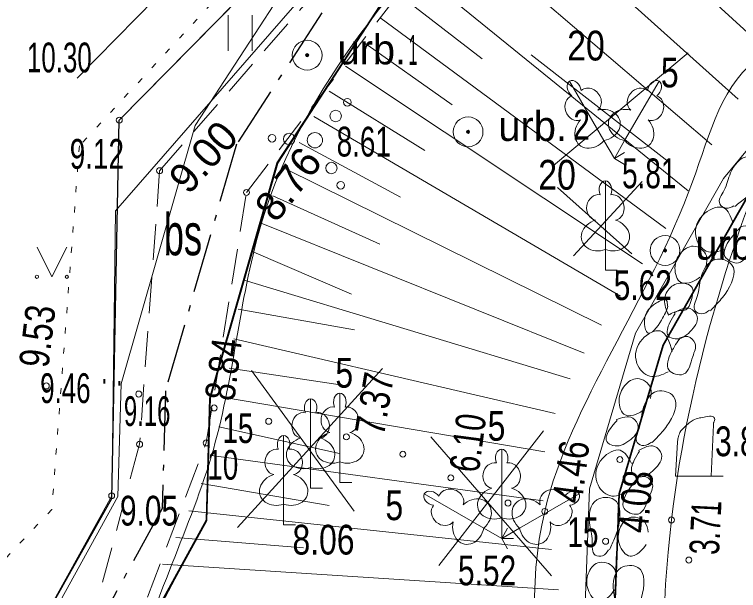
# Model space of a CAD drawing. Extents: x 514052 to 514314, y 297701 to 297876.
# Drawn here: x 514231.91 to 514244.06, y 297772.58 to 297782.26 of the extents above; entities that cross this region are included whole.
import ezdxf
from ezdxf.enums import TextEntityAlignment as Align

# ---------------------------------------------------------------- set-up
doc = ezdxf.new("R2010")
doc.units = 0
doc.header["$LTSCALE"] = 0.2
for name, pattern in [('DOT_DASHED', [7.7, 5, -1.2, 0.3, -1.2]), ('DOTTED', [1.5, 0.3, -1.2]), ('MEDIUM_DASHED', [4.5, 3, -1.5])]:
    doc.linetypes.add(name, pattern=pattern)
for name, color, linetype, lineweight in [('1', 7, 'Continuous', 13), ('11', 7, 'Continuous', 35), ('19', 7, 'Continuous', 25), ('35', 7, 'Continuous', 25), ('5', 7, 'Continuous', 13), ('55', 7, 'Continuous', 13), ('57', 7, 'DOTTED', 13), ('6', 7, 'Continuous', 13), ('61', 7, 'Continuous', 13), ('62', 7, 'Continuous', 13), ('63', 7, 'Continuous', 13)]:
    doc.layers.add(name, color=color, linetype=linetype, lineweight=lineweight)
for name, color, linetype in [('10', 7, 'Continuous'), ('12', 7, 'Continuous'), ('8', 7, 'Continuous')]:
    doc.layers.add(name, color=color, linetype=linetype)

msp = doc.modelspace()

# ---------------------------------------------------------------- hatches: boundary and pattern name
at = {"layer": '6'}
for points in [[(514236.8473, 297781.5754, 1), (514236.7942, 297781.5754, 1)], [(514239.5483, 297780.2884, 1), (514239.4952, 297780.2884, 1)], [(514242.854, 297778.2947, 1), (514242.801, 297778.2947, 1)]]:
    msp.add_hatch(color=256, dxfattribs=at).paths.add_polyline_path(points)

# ---------------------------------------------------------------- linework, layer by layer
at = {"layer": '1'}
for p, q in [((514240.629, 297785.257), (514244.562, 297781.634)), ((514239.956, 297784.518), (514244.054, 297780.838)), ((514239.295, 297783.768), (514243.612, 297780.068)), ((514238.654, 297783), (514243.216, 297779.299)), ((514238.343, 297782.608), (514239.757, 297781.513)), ((514238.041, 297782.21), (514242.841, 297778.665)), ((514237.747, 297781.805), (514239.252, 297780.744)), ((514237.464, 297781.393), (514242.451, 297778.071)), ((514237.192, 297780.973), (514238.797, 297779.976)), ((514236.933, 297780.546), (514242.082, 297777.527)), ((514236.688, 297780.11), (514238.39, 297779.192)), ((514236.458, 297779.666), (514241.759, 297777.039)), ((514236.244, 297779.214), (514238.041, 297778.403)), ((514236.047, 297778.755), (514241.471, 297776.57)), ((514235.885, 297778.282), (514237.565, 297777.563)), ((514235.762, 297777.798), (514241.238, 297776.14)), ((514235.665, 297777.307), (514237.618, 297776.964)), ((514235.587, 297776.813), (514240.986, 297775.559)), ((514235.513, 297776.319), (514237.484, 297776.024)), ((514235.435, 297775.825), (514240.811, 297774.914)), ((514235.339, 297775.334), (514237.363, 297774.888)), ((514235.215, 297774.85), (514240.784, 297774.089)), ((514235.044, 297774.38), (514237.188, 297774.014)), ((514234.837, 297773.925), (514240.922, 297773.271)), ((514234.615, 297773.477), (514236.758, 297773.298)), ((514234.394, 297773.029), (514241.041, 297772.596))]:
    msp.add_line(p, q, dxfattribs=at)
msp.add_spline([(514260.862, 297805.466), (514258.749, 297804.839), (514257.459, 297803.011), (514254.953, 297800.933), (514250.105, 297795.245), (514240.136, 297784.718), (514236.07, 297778.812), (514235.246, 297774.955), (514233.92, 297771.109), (514234.456, 297764.804)], degree=3, dxfattribs=at)
at = {"layer": '11'}
msp.add_lwpolyline([(514232.958, 297781.189), (514235.602, 297783.886), (514241.55, 297789.883)], dxfattribs=at)
at = {"layer": '19', "lineweight": 13}
msp.add_spline([(514243.205, 297765.058), (514242.936, 297773.769), (514245.025, 297781.038), (514246.54, 297783.925), (514249.054, 297787.013), (514257.225, 297795.21), (514260.154, 297798.886), (514267.863, 297801.516), (514273.305, 297805.826), (514276.583, 297807.615)], degree=3, dxfattribs=at)
at = {"layer": '35'}
msp.add_lwpolyline([(514231.97, 297771.331), (514233.541, 297774.128), (514233.667, 297780.485), (514240.255, 297787.177), (514246.843, 297793.868), (514250.774, 297798.68), (514254.387, 297803.352), (514256.058, 297805.511), (514258.694, 297808.915), (514260.151, 297809.248), (514268.632, 297811.186)], dxfattribs=at)
at = {"layer": '35', "lineweight": 35}
msp.add_lwpolyline([(514271.3, 297810.152), (514259.606, 297807.499), (514252.681, 297798.474), (514245.829, 297790.57), (514238.515, 297783.139), (514236.323, 297779.764), (514235.19, 297775.821), (514235.133, 297773.758), (514233.372, 297770.559)], dxfattribs=at)
at = {"layer": '5'}
for p, q in [((514235.496, 297781.649), (514235.496, 297782.249)), ((514235.896, 297781.649), (514235.896, 297782.249)), ((514241.227, 297781.14), (514241.803, 297780.142)), ((514242.727, 297781.14), (514242.15, 297780.142)), ((514241.421, 297780.984), (514241.419, 297780.984)), ((514242.688, 297780.894), (514242.688, 297780.895)), ((514241.803, 297780.142), (514241.977, 297779.841)), ((514242.15, 297780.142), (514241.977, 297779.841)), ((514241.977, 297779.841), (514242.15, 297779.941)), ((514241.977, 297779.841), (514242.15, 297779.741)), ((514241.827, 297779.463), (514241.827, 297778.31)), ((514241.917, 297779.231), (514241.916, 297779.232)), ((514241.827, 297778.31), (514241.827, 297777.963)), ((514241.827, 297777.963), (514242.027, 297777.963)), ((514237.369, 297775.897), (514237.369, 297774.744)), ((514236.879, 297775.803), (514236.879, 297774.65)), ((514237.459, 297775.665), (514237.458, 297775.666)), ((514236.969, 297775.571), (514236.968, 297775.572)), ((514243.605, 297774.502), (514243.639, 297775.367)), ((514236.426, 297775.188), (514236.426, 297774.035)), ((514236.516, 297774.956), (514236.515, 297774.957)), ((514240.086, 297774.958), (514240.086, 297773.805)), ((514237.369, 297774.744), (514237.369, 297774.397)), ((514240.176, 297774.726), (514240.175, 297774.727)), ((514236.879, 297774.65), (514236.879, 297774.303)), ((514243.605, 297774.502), (514243.005, 297774.502)), ((514243.605, 297774.502), (514243.805, 297774.502)), ((514237.369, 297774.397), (514237.569, 297774.397)), ((514236.879, 297774.303), (514237.079, 297774.303)), ((514238.787, 297774.208), (514239.785, 297773.632)), ((514241.385, 297774.208), (514240.386, 297773.632)), ((514239.033, 297774.17), (514239.032, 297774.169)), ((514236.426, 297774.035), (514236.426, 297773.688)), ((514241.229, 297774.014), (514241.229, 297774.016)), ((514240.086, 297773.805), (514240.086, 297773.458)), ((514236.426, 297773.688), (514236.626, 297773.688)), ((514239.785, 297773.632), (514240.086, 297773.458)), ((514240.386, 297773.632), (514240.086, 297773.458)), ((514240.086, 297773.458), (514240.186, 297773.631)), ((514240.086, 297773.458), (514240.286, 297773.458)), ((514240.086, 297773.458), (514240.186, 297773.285))]:
    msp.add_line(p, q, dxfattribs=at)
for points in [[(514232.286, 297778.354), (514232.536, 297777.854), (514232.786, 297778.354)], [(514243.036, 297775.075), (514243.005, 297774.502), (514243.305, 297774.502), (514243.605, 297774.502)]]:
    msp.add_lwpolyline(points, dxfattribs=at)
for centre, radius in [((514237.495, 297780.7865), 0.064), ((514237.2985, 297780.5548), 0.096), ((514236.517, 297780.1679), 0.096), ((514236.951, 297780.1471), 0.128), ((514236.2326, 297780.1814), 0.064), ((514237.2274, 297779.6803), 0.096), ((514237.3849, 297779.391), 0.064), ((514232.2855, 297777.8537), 0.028), ((514232.7855, 297777.8537), 0.0263)]:
    msp.add_circle(centre, radius, dxfattribs=at)
for centre, major_axis, ratio, start_param, end_param in [((514241.3023, 297781.0105), (0.075, -0.1298), 0.707107, 3.1453698, 5.2874846), ((514241.3016, 297781.0101), (0.075, -0.1298), 0.707107, 0.9957007, 3.1378155), ((514242.6523, 297781.0101), (-0.075, -0.1298), 0.707107, 3.1453698, 5.2874846), ((514242.6516, 297781.0105), (-0.075, -0.1298), 0.707107, 0.9957007, 3.1378155), ((514241.5605, 297780.8191), (0.1397, -0.1646), 0.861323, 6.2831853, 9.424778), ((514242.3934, 297780.8191), (-0.1397, -0.1646), 0.861323, 3.1415927, 6.2831853), ((514241.3382, 297780.6908), (0.0727, -0.2033), 0.861323, 3.1415927, 6.2831853), ((514242.6157, 297780.6908), (-0.0727, -0.2033), 0.861323, 6.2831853, 9.424778), ((514241.7581, 297780.3994), (-0.3133, -0.071), 0.814445, 1.5311707, 4.712389), ((514242.1958, 297780.3994), (0.3133, -0.071), 0.814445, 1.5707963, 4.7520146), ((514241.6029, 297780.3098), (0.2182, 0.2358), 0.814445, 1.5707963, 4.7520146), ((514242.351, 297780.3098), (-0.2182, 0.2358), 0.814445, 1.5311707, 4.712389), ((514241.8274, 297779.3132), (0, -0.1499), 0.707107, 3.1453698, 5.2874846), ((514241.8265, 297779.3132), (0, -0.1499), 0.707107, 0.9957007, 3.1378155), ((514241.6987, 297779.0184), (-0.0387, -0.2124), 0.861323, 3.1415927, 6.2831853), ((514241.9552, 297779.0184), (0.0387, -0.2124), 0.861323, 6.2831853, 9.424778), ((514241.7374, 297778.5561), (0.3068, 0.0951), 0.814445, 1.5707963, 4.7520146), ((514241.9165, 297778.5561), (-0.3068, 0.0951), 0.814445, 1.5311707, 4.712389), ((514237.3694, 297775.7472), (0, -0.1499), 0.707107, 3.1453698, 5.2874846), ((514237.3685, 297775.7472), (0, -0.1499), 0.707107, 0.9957007, 3.1378155), ((514236.8794, 297775.6532), (0, -0.1499), 0.707107, 3.1453698, 5.2874846), ((514236.8785, 297775.6532), (0, -0.1499), 0.707107, 0.9957007, 3.1378155), ((514237.2407, 297775.4524), (-0.0387, -0.2124), 0.861323, 3.1415927, 6.2831853), ((514237.4972, 297775.4524), (0.0387, -0.2124), 0.861323, 6.2831853, 9.424778), ((514236.7507, 297775.3584), (-0.0387, -0.2124), 0.861323, 3.1415927, 6.2831853), ((514237.0072, 297775.3584), (0.0387, -0.2124), 0.861323, 6.2831853, 9.424778), ((514236.4264, 297775.0382), (0, -0.1499), 0.707107, 3.1453698, 5.2874846), ((514236.4255, 297775.0382), (0, -0.1499), 0.707107, 0.9957007, 3.1378155), ((514237.2794, 297774.9901), (0.3068, 0.0951), 0.814445, 1.5707963, 4.7520146), ((514237.4585, 297774.9901), (-0.3068, 0.0951), 0.814445, 1.5311707, 4.712389), ((514236.7894, 297774.8961), (0.3068, 0.0951), 0.814445, 1.5707963, 4.7520146), ((514236.9685, 297774.8961), (-0.3068, 0.0951), 0.814445, 1.5311707, 4.712389), ((514236.2977, 297774.7434), (-0.0387, -0.2124), 0.861323, 3.1415927, 6.2831853), ((514236.5542, 297774.7434), (0.0387, -0.2124), 0.861323, 6.2831853, 9.424778), ((514240.0864, 297774.8082), (0, -0.1499), 0.707107, 3.1453698, 5.2874846), ((514240.0855, 297774.8082), (0, -0.1499), 0.707107, 0.9957007, 3.1378155), ((514239.9577, 297774.5134), (-0.0387, -0.2124), 0.861323, 3.1415927, 6.2831853), ((514240.2142, 297774.5134), (0.0387, -0.2124), 0.861323, 6.2831853, 9.424778), ((514236.3364, 297774.2811), (0.3068, 0.0951), 0.814445, 1.5707963, 4.7520146), ((514236.5155, 297774.2811), (-0.3068, 0.0951), 0.814445, 1.5311707, 4.712389), ((514239.2363, 297774.0969), (0.2033, -0.0727), 0.861323, 6.2831853, 9.424778), ((514238.917, 297774.1335), (0.1298, -0.075), 0.707107, 3.1453698, 5.2874846), ((514238.9166, 297774.1328), (0.1298, -0.075), 0.707107, 0.9957007, 3.1378155), ((514239.9964, 297774.0511), (0.3068, 0.0951), 0.814445, 1.5707963, 4.7520146), ((514240.1755, 297774.0511), (-0.3068, 0.0951), 0.814445, 1.5311707, 4.712389), ((514240.9356, 297774.0969), (-0.2033, -0.0727), 0.861323, 3.1415927, 6.2831853), ((514241.2553, 297774.1328), (-0.1298, -0.075), 0.707107, 3.1453698, 5.2874846), ((514241.2549, 297774.1335), (-0.1298, -0.075), 0.707107, 0.9957007, 3.1378155), ((514239.6173, 297773.8322), (-0.2358, -0.2182), 0.814445, 1.5311707, 4.712389), ((514240.5546, 297773.8322), (0.2358, -0.2182), 0.814445, 1.5707963, 4.7520146), ((514239.108, 297773.8746), (0.1646, -0.1397), 0.861323, 3.1415927, 6.2831853), ((514241.0639, 297773.8746), (-0.1646, -0.1397), 0.861323, 6.2831853, 9.424778), ((514239.5277, 297773.677), (0.071, 0.3133), 0.814445, 1.5707963, 4.7520146), ((514240.6442, 297773.677), (-0.071, 0.3133), 0.814445, 1.5311707, 4.712389)]:
    msp.add_ellipse(centre, major_axis=major_axis, ratio=ratio, start_param=start_param, end_param=end_param, dxfattribs=at)
msp.add_spline([(514243.639, 297775.367), (514243.643, 297775.398), (514243.646, 297775.409), (514243.661, 297775.471), (514243.631, 297775.506), (514243.509, 297775.5), (514243.405, 297775.482), (514243.299, 297775.443), (514243.234, 297775.399), (514243.159, 297775.335), (514243.079, 297775.237), (514243.048, 297775.148), (514243.036, 297775.074)], degree=3, dxfattribs=at)
at = {"layer": '55'}
msp.add_lwpolyline([(514217.339, 297769.84), (514231.97, 297771.331), (514233.541, 297774.128), (514233.602, 297778.964), (514248.877, 297796.499), (514258.817, 297808.985), (514270.863, 297811.577), (514272.894, 297813.849)], dxfattribs=at)
at = {"layer": '57', "lineweight": 25}
msp.add_line((514243.763, 297791.654), (514232.997, 297780.053), dxfattribs=at)
at = {"layer": '57'}
msp.add_lwpolyline([(514232.997, 297780.053), (514232.534, 297773.947), (514230.974, 297772.287), (514219.876, 297771.165)], dxfattribs=at)
at = {"layer": '6'}
for centre, radius in [((514236.821, 297781.5756), 0.25), ((514236.8208, 297781.5754), 0.0265), ((514233.6669, 297780.4851), 0.05), ((514239.522, 297780.2886), 0.25), ((514239.5218, 297780.2884), 0.0265), ((514234.344, 297779.6351), 0.05), ((514235.8019, 297779.2701), 0.05), ((514242.8277, 297778.2949), 0.25), ((514242.8275, 297778.2947), 0.0265), ((514232.4417, 297776.0202), 0.05), ((514233.9939, 297775.8841), 0.05), ((514235.2589, 297775.6502), 0.05), ((514236.175, 297775.4261), 0.05), ((514237.479, 297775.1651), 0.05), ((514234.0079, 297775.0401), 0.05), ((514235.126, 297775.0621), 0.05), ((514238.4269, 297774.8731), 0.05), ((514242.0699, 297774.7831), 0.05), ((514239.2319, 297774.4762), 0.05), ((514233.539, 297774.1751), 0.05), ((514240.192, 297774.0532), 0.05), ((514240.8089, 297773.9121), 0.05), ((514242.936, 297773.7692), 0.05), ((514241.8309, 297773.4111), 0.05), ((514243.2274, 297773.0956), 0.05)]:
    msp.add_circle(centre, radius, dxfattribs=at)
at = {"layer": '61'}
msp.add_lwpolyline([(514219.342, 297770.059), (514231.967, 297771.335), (514233.539, 297774.175), (514233.667, 297780.485), (514246.843, 297793.868)], dxfattribs=at)
at = {"layer": '62'}
msp.add_spline([(514242.228, 297765.875), (514240.809, 297773.912), (514243.289, 297779.448), (514244.466, 297781.572), (514244.559, 297781.63), (514245.987, 297783.723), (514248.871, 297787.176), (514251.243, 297789.878), (514252.476, 297791.159), (514253.723, 297792.429), (514256.513, 297795.415), (514260.533, 297799.834), (514263.587, 297801.907), (514261.268, 297805.481)], degree=3, dxfattribs=at)
at = {"layer": '63'}
for p, q in [((514243.219, 297781.617), (514240.955, 297779.725)), ((514240.583, 297781.583), (514242.881, 297779.793)), ((514242.442, 297779.455), (514241.293, 297778.205)), ((514241.023, 297779.354), (514242.273, 297778.239)), ((514238.083, 297776.313), (514235.651, 297773.644)), ((514235.887, 297776.279), (514237.61, 297773.914)), ((514238.894, 297775.164), (514240.921, 297772.833)), ((514240.786, 297775.266), (514239.029, 297773.002))]:
    msp.add_line(p, q, dxfattribs=at)
at = {"layer": '63', "linetype": 'MEDIUM_DASHED'}
for points in [[(514231.583, 297765.652), (514232.855, 297769.107), (514235.126, 297775.062), (514235.802, 297779.27), (514240.035, 297784.801), (514250.098, 297795.488), (514254.893, 297801.043), (514257.448, 297803.118), (514259.485, 297807.223), (514261.814, 297808.455), (514265.145, 297808.86), (514272.105, 297811.112)], [(514249.225, 297796.455), (514239.453, 297785.495), (514234.344, 297779.635), (514234.008, 297775.04), (514233.159, 297771.888), (514231.647, 297770.296), (514228.019, 297768.169)]]:
    msp.add_lwpolyline(points, dxfattribs=at)
at = {"layer": '63', "linetype": 'DOT_DASHED', "lineweight": 25}
for points in [[(514271.134, 297810.883), (514259.176, 297808.17), (514252.1, 297798.948), (514245.278, 297791.079), (514237.927, 297783.611), (514235.633, 297780.079), (514234.443, 297775.937), (514234.388, 297773.96), (514232.332, 297770.225), (514229.92, 297766.887)], [(514241.744, 297765.925), (514242.057, 297774.207), (514242.797, 297776.707), (514244.225, 297779.218), (514245.964, 297781.323), (514250.712, 297786.706), (514257.523, 297794.362), (514261.299, 297799.094), (514264.423, 297802.109), (514265.043, 297802.596), (514265.222, 297802.656), (514267.352, 297803.342), (514273.537, 297806.201)]]:
    msp.add_lwpolyline(points, dxfattribs=at)
at = {"layer": '63', "lineweight": 35}
msp.add_lwpolyline([(514241.744, 297765.925), (514242.057, 297774.207), (514242.797, 297776.707), (514244.225, 297779.218), (514245.094, 297780.271), (514245.964, 297781.323), (514248.338, 297784.015), (514250.712, 297786.706), (514254.118, 297790.534), (514257.523, 297794.362), (514259.411, 297796.728), (514261.299, 297799.094), (514262.861, 297800.601), (514264.423, 297802.109), (514265.043, 297802.596), (514267.352, 297803.342), (514273.537, 297806.201)], dxfattribs=at)
at = {"layer": '63'}
for points in [[(514249.255, 297794.522), (514245.829, 297790.57), (514241.829, 297786.505), (514238.515, 297783.139), (514236.314, 297779.769), (514235.179, 297775.815), (514235.126, 297773.769), (514232.94, 297769.786), (514230.528, 297766.448), (514229.312, 297767.326), (514231.675, 297770.587), (514233.643, 297774.162), (514233.696, 297776.053), (514234.943, 297780.394), (514237.339, 297784.083), (514241.033, 297787.835), (514244.727, 297791.588)], [(514233.812, 297771.282), (514235.126, 297773.769), (514235.179, 297775.815), (514236.314, 297779.769), (514238.515, 297783.139), (514239.32, 297783.956), (514239.882, 297784.527), (514240.622, 297785.277), (514243.036, 297787.732), (514245.182, 297789.914), (514246.011, 297790.776), (514246.248, 297791.053), (514247.856, 297792.907)], [(514253.744, 297790.866), (514250.746, 297787.504), (514247.963, 297784.346), (514245.584, 297781.648), (514243.812, 297779.503), (514242.875, 297777.861), (514242.334, 297776.904), (514242.334, 297776.904), (514241.56, 297774.289), (514241.402, 297770.117)]]:
    msp.add_lwpolyline(points, dxfattribs=at)
at = {"layer": '63', "lineweight": 35}
msp.add_spline([(514215.228, 297765.323), (514215.206, 297772.763), (514216.383, 297781.396), (514219.324, 297786.104), (514225.403, 297788.655), (514229.52, 297789.636), (514235.599, 297788.066)], degree=3, dxfattribs=at)
at = {"layer": '63'}
for points in [[(514243.985, 297779.046), (514243.851, 297779.007), (514243.748, 297779.077), (514243.819, 297779.307), (514243.928, 297779.599), (514244.22, 297779.875), (514244.476, 297779.745), (514244.287, 297779.272), (514244.089, 297779.105), (514244, 297779.036)], [(514243.967, 297778.759), (514243.814, 297779.011), (514243.498, 297778.923), (514243.344, 297778.534), (514243.521, 297778.286), (514243.837, 297778.31)], [(514244.106, 297778.699), (514243.918, 297778.482), (514243.834, 297778.196), (514244.06, 297778.087), (514244.264, 297778.358), (514244.338, 297778.566), (514244.235, 297778.699), (514244.106, 297778.699)], [(514243.519, 297778.032), (514243.522, 297778.208), (514243.302, 297778.368), (514243.09, 297778.25), (514242.995, 297778), (514243.098, 297777.756), (514243.281, 297777.77), (514243.414, 297777.846)], [(514243.573, 297777.291), (514243.447, 297777.231), (514243.334, 297777.283), (514243.367, 297777.522), (514243.428, 297777.827), (514243.673, 297778.146), (514243.946, 297778.059), (514243.835, 297777.562), (514243.666, 297777.365), (514243.589, 297777.283)], [(514242.884, 297777.218), (514242.82, 297777.463), (514242.917, 297777.674), (514243.146, 297777.745), (514243.275, 297777.685), (514243.266, 297777.454), (514243.175, 297777.299), (514243.085, 297777.286), (514242.882, 297777.209)], [(514242.877, 297777.358), (514242.768, 297777.123), (514242.533, 297776.913), (514242.483, 297777.056), (514242.684, 297777.416), (514242.852, 297777.458), (514242.868, 297777.358)], [(514242.982, 297777.247), (514243.251, 297777.319), (514243.367, 297777.188), (514243.247, 297776.929), (514242.997, 297776.81), (514242.884, 297776.862), (514242.908, 297777.085), (514242.999, 297777.239)], [(514242.95, 297776.6), (514242.745, 297776.944), (514242.447, 297776.807), (514242.357, 297776.399), (514242.571, 297776.182), (514242.879, 297776.256)], [(514243.083, 297776.828), (514242.932, 297776.584), (514242.894, 297776.288), (514243.135, 297776.216), (514243.293, 297776.516), (514243.333, 297776.733), (514243.21, 297776.848), (514243.083, 297776.828)], [(514242.582, 297775.808), (514242.585, 297775.984), (514242.365, 297776.144), (514242.153, 297776.026), (514242.058, 297775.776), (514242.161, 297775.532), (514242.344, 297775.546), (514242.477, 297775.622)], [(514242.598, 297775.077), (514242.472, 297775.017), (514242.359, 297775.069), (514242.392, 297775.308), (514242.453, 297775.613), (514242.698, 297775.932), (514242.971, 297775.845), (514242.86, 297775.348), (514242.691, 297775.151), (514242.614, 297775.069)], [(514242.008, 297775.452), (514242.285, 297775.48), (514242.379, 297775.332), (514242.219, 297775.096), (514241.954, 297775.018), (514241.85, 297775.087), (514241.91, 297775.304), (514242.024, 297775.441)], [(514242.383, 297774.933), (514242.652, 297775.005), (514242.768, 297774.874), (514242.648, 297774.615), (514242.398, 297774.496), (514242.285, 297774.548), (514242.309, 297774.771), (514242.4, 297774.925)], [(514242.266, 297774.715), (514242.075, 297774.939), (514241.777, 297774.802), (514241.687, 297774.394), (514241.901, 297774.177), (514242.209, 297774.251)], [(514242.376, 297774.483), (514242.205, 297774.253), (514242.141, 297773.962), (514242.375, 297773.869), (514242.559, 297774.155), (514242.617, 297774.367), (514242.504, 297774.493), (514242.376, 297774.483)], [(514241.878, 297773.266), (514241.78, 297773.168), (514241.656, 297773.178), (514241.606, 297773.414), (514241.56, 297773.723), (514241.682, 297774.105), (514241.969, 297774.115), (514242.033, 297773.611), (514241.941, 297773.369), (514241.896, 297773.265)], [(514242.547, 297773.565), (514242.49, 297773.731), (514242.228, 297773.807), (514242.069, 297773.624), (514242.064, 297773.357), (514242.244, 297773.162), (514242.411, 297773.238), (514242.511, 297773.355)], [(514242.017, 297772.807), (514241.961, 297772.973), (514241.7, 297773.049), (514241.54, 297772.866), (514241.535, 297772.599), (514241.715, 297772.404), (514241.883, 297772.479), (514241.982, 297772.596)], [(514242.281, 297772.124), (514242.182, 297772.025), (514242.059, 297772.036), (514242.008, 297772.272), (514241.962, 297772.58), (514242.085, 297772.962), (514242.371, 297772.973), (514242.435, 297772.468), (514242.344, 297772.226), (514242.299, 297772.122)]]:
    msp.add_spline(points, degree=3, dxfattribs=at)

# ---------------------------------------------------------------- texts
at = {"layer": '10', "width": 0.65}
msp.add_text('bs', height=0.7, dxfattribs=at).set_placement((514234.735, 297778.215), align=Align.CENTER)
at = {"layer": '12'}
for s, width, p in [(' 20', 0.85, (514241.027, 297781.487)), (' 5', 0.8, (514242.61, 297781.035)), (' 20', 0.85, (514240.542, 297779.317)), (' 5', 0.8, (514237.146, 297775.991)), (' 15', 0.7, (514235.268, 297775.061)), (' 5', 0.8, (514239.702, 297775.1)), (' 10', 0.7, (514235.014, 297774.445)), (' 5', 0.8, (514237.986, 297773.766)), (' 15', 0.7, (514241.06, 297773.313))]:
    msp.add_text(s, height=0.5, dxfattribs=dict(at, width=width)).set_placement(p)
at = {"layer": '6'}
for p in [(514237.329, 297781.423), (514240.03, 297780.136), (514243.336, 297778.142)]:
    msp.add_text('urb.', height=0.5, dxfattribs=at).set_placement(p)
for s, width, p in [('1', 0.4, (514238.5965, 297781.413)), ('2', 0.75, (514241.428, 297780.159))]:
    msp.add_text(s, height=0.5, dxfattribs=dict(at, width=width)).set_placement(p, align=Align.CENTER)
at = {"layer": '8'}
for s, width, p in [('10.30', 0.65, (514232.117, 297781.288)), (' 8.61', 0.7, (514237.185, 297779.874)), (' 9.12', 0.7, (514232.705, 297779.668)), (' 5.81', 0.7, (514241.977, 297779.341)), (' 5.62', 0.75, (514241.827, 297777.463)), ('9.46', 0.65, (514232.339, 297775.733)), ('.', 0.5, (514233.371, 297776.059)), ('.', 0.5, (514233.62, 297776.024)), ('9.16', 0.6, (514233.744, 297775.347)), (' 3.83', 0.75, (514243.528, 297774.84)), (' 9.05', 0.75, (514233.539, 297773.675)), (' 8.06', 0.8, (514236.426, 297773.188)), (' 5.52', 0.75, (514239.213, 297772.671))]:
    msp.add_text(s, height=0.5, dxfattribs=dict(at, width=width)).set_placement(p)
for s, rotation, p in [(' 9.00', 48.239, (514234.707, 297779.077)), (' 8.76', 52.455, (514236.189, 297778.597))]:
    msp.add_text(s, height=0.5, rotation=rotation, dxfattribs=at).set_placement(p)
for s, rotation, width, p in [(' 9.53', 83.27, 0.8, (514232.46, 297776.164)), (' 8.84', 82.774, 0.8, (514235.577, 297775.605)), (' 7.37', 80.492, 0.8, (514238.084, 297775.021)), (' 6.10', 82.506, 0.75, (514239.683, 297774.411)), (' 4.46', 82.69, 0.8, (514241.412, 297773.884)), (' 4.08', 84.58, 0.8, (514242.521, 297773.388)), (' 3.71', 87.239, 0.7, (514243.727, 297773.045))]:
    msp.add_text(s, height=0.5, rotation=rotation, dxfattribs=dict(at, width=width)).set_placement(p)

doc.saveas('drawing.dxf')
